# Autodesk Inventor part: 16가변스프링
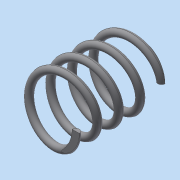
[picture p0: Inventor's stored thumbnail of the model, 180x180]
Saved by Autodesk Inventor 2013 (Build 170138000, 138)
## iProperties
Created: 2015-09
Part Number: 16가변스프링
Material: 일반
Document SubType Name: Modeling
Designer: dgall
Density: 1 g/cm^3
Author: dgall
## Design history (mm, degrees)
sketch "스케치1"
  geometry: L1 (8, 0)-(0, 0); L2 (0, 0)-(0, 24); L3 (0, 24)-(8, 24); C1 r 1 at (8, 0)
  constraints: 6 end point, 1 centre point, 1 coincident, 1 horizontal, 1 parallel, 1 perpendicular, 1 vertical alignment
  dimensions: "d0" = 24 distance of L1.end L2.end (derived); "d1" = 16 diameter of L1.start L2; "d2" = 2 diameter of C1
feature "코일1" pitch "d3" = 10; turns "d5" = 4; dims "d4" = 24 (= d0), "d6" = 0, angle "d7" = 90 deg, angle "d8" = 90 deg, "d9" = 0, "d10" = 0
feature "분할1"
node "작업 평면1"
feature "분할2"
node "솔리드1"
other parameters: "d11" = 24
